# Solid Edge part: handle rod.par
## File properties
Title: Handle Rod
Author: Deepak Maini
Template: Normal.par
Last saved by: Robert a Rhodes jr
Revision: 6
Application: Solid Edge
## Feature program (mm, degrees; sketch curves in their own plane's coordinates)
sketch for "unnamed Protrusion 1" plane through (0, 0, 0) normal (0, -1, 0) x-axis (1, 0, 0)
  circle centre (0, 0) radius 3.9624
extrude "unnamed Protrusion 1" add finite 130.175 symmetric
sketch for "unnamed Cutout 1" plane through (0, 0, 0) normal (0, 0, 1) x-axis (1, 0, 0)
  circle centre (0, 57.4675) radius 1.905
extrude "unnamed Cutout 1" cut finite 101.6 symmetric
mirror "unnamed Mirror 1" of "unnamed Cutout 1"
pattern "unnamed Pattern 1"
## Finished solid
Body 1: solid body, 5 faces, 6 edges, 0 vertices.
  Faces by surface: cylinder 3, plane 2
  Edges by curve: intersection 4, circle 2
Bounding box of the edges (mm): 7.925 x 130.175 x 7.925, from (-3.9624, -65.0875, -3.9624) to (3.9624, 65.0875, 3.9624).
Cylindrical faces by radius (mm): R1.905 x2, R3.9624 x1
Planar faces by outward normal: +y 1, -y 1
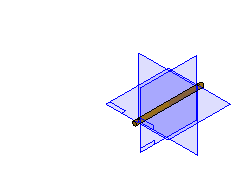
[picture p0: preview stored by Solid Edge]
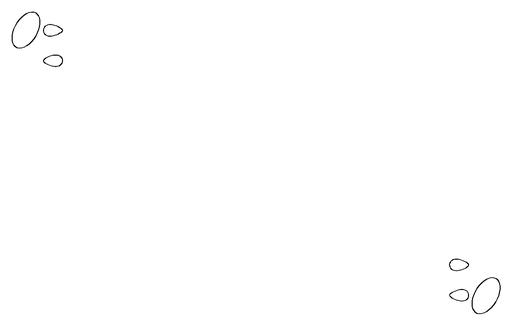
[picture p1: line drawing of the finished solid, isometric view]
